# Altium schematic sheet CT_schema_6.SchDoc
size 274 x 160 mm
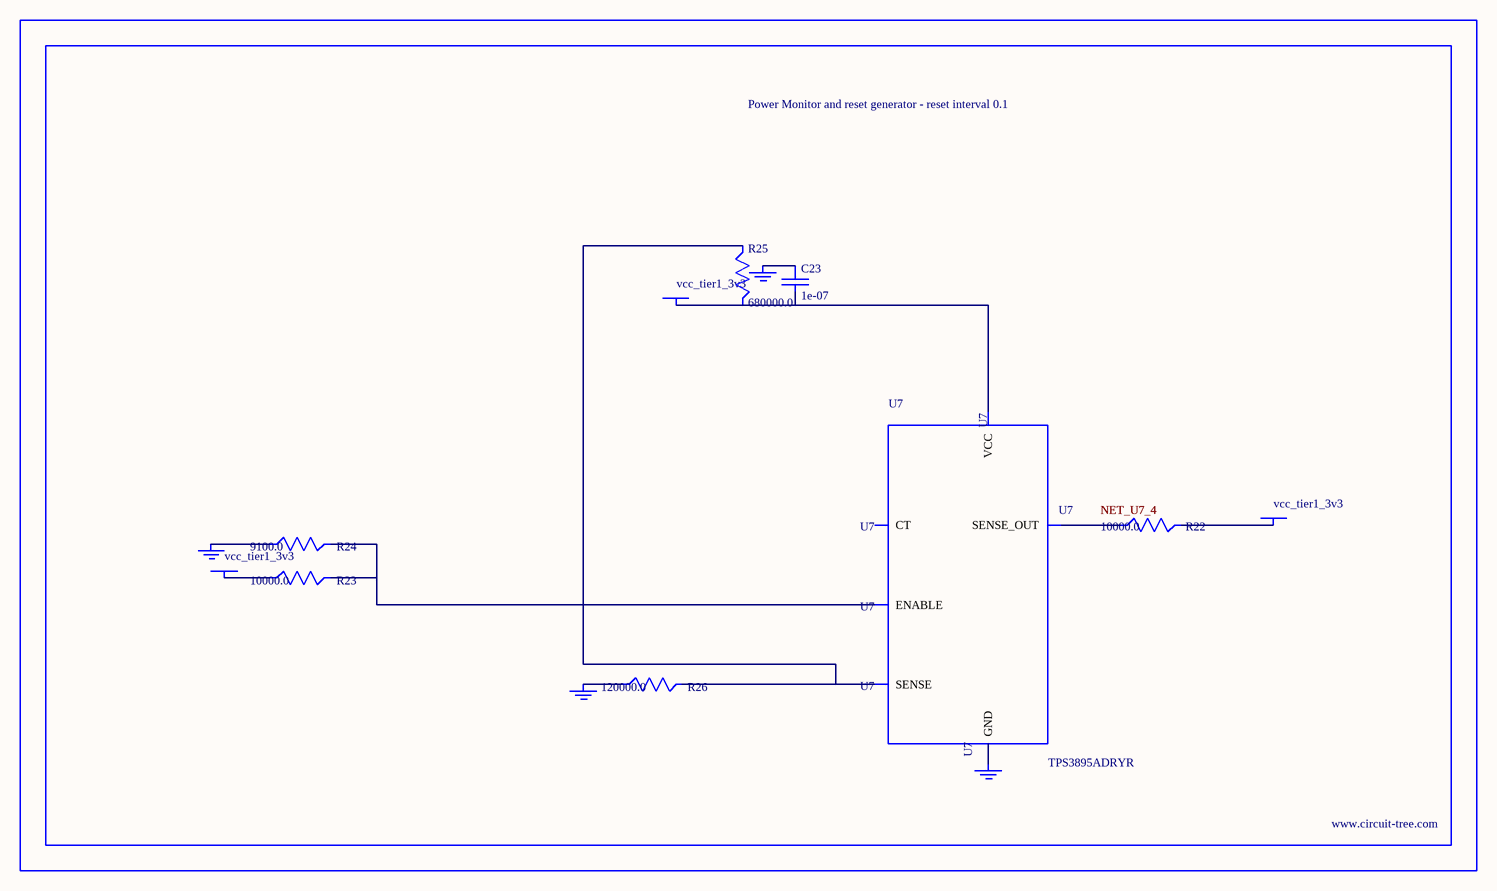
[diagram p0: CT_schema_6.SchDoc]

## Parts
BORDER5  (no value)
C23  1e-07  [C0402]
GND_INSTANCE_5_0  (no value)
GND_INSTANCE_5_1  (no value)
GND_INSTANCE_5_2  (no value)
GND_INSTANCE_5_3  (no value)
POWER_INSTANCE_5_0  vcc_tier1_3v3
POWER_INSTANCE_5_1  vcc_tier1_3v3
POWER_INSTANCE_5_2  vcc_tier1_3v3
R22  10000.0  [R0603]
R23  10000.0  [R0603]
R24  9100.0  [R0603]
R25  680000.0  [R0603]
R26  120000.0  [R0603]
U7  TPS3895ADRYR  [SON-6]

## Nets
NetC23_1: C23.1 GND_INSTANCE_5_2.0(GND)
NetC23_2: C23.2 POWER_INSTANCE_5_2.0(PWR) R25.2 U7.6(VCC)
NetGND_INSTANCE_5_0_0: GND_INSTANCE_5_0.0(GND) R24.1
NetGND_INSTANCE_5_1_0: GND_INSTANCE_5_1.0(GND) R26.1
NetGND_INSTANCE_5_3_0: GND_INSTANCE_5_3.0(GND) U7.2(GND)
NetPOWER_INSTANCE_5_0_0: POWER_INSTANCE_5_0.0(PWR) R23.1
NetPOWER_INSTANCE_5_1_0: POWER_INSTANCE_5_1.0(PWR) R22.2
NetR22_1: R22.1 U7.4(SENSE_OUT)
NetR23_2: R23.2 R24.2 U7.1(ENABLE)
NetR25_1: R25.1 R26.2 U7.3(SENSE)

Not connected (* = marked no-connect by the designer): U7 5(CT)

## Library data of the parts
BORDER5 = BORDER_PAGE5
C23 = C0402C104K3RACTU
GND_INSTANCE_5_0-GND_INSTANCE_5_3 = GND
POWER_INSTANCE_5_0-POWER_INSTANCE_5_2 = PWR
R22 R23 = RC0603JR-0710KL
R24 = RC0603JR-079K1L
R25 = RC0603JR-07680KL
R26 = RC0603JR-07120KL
